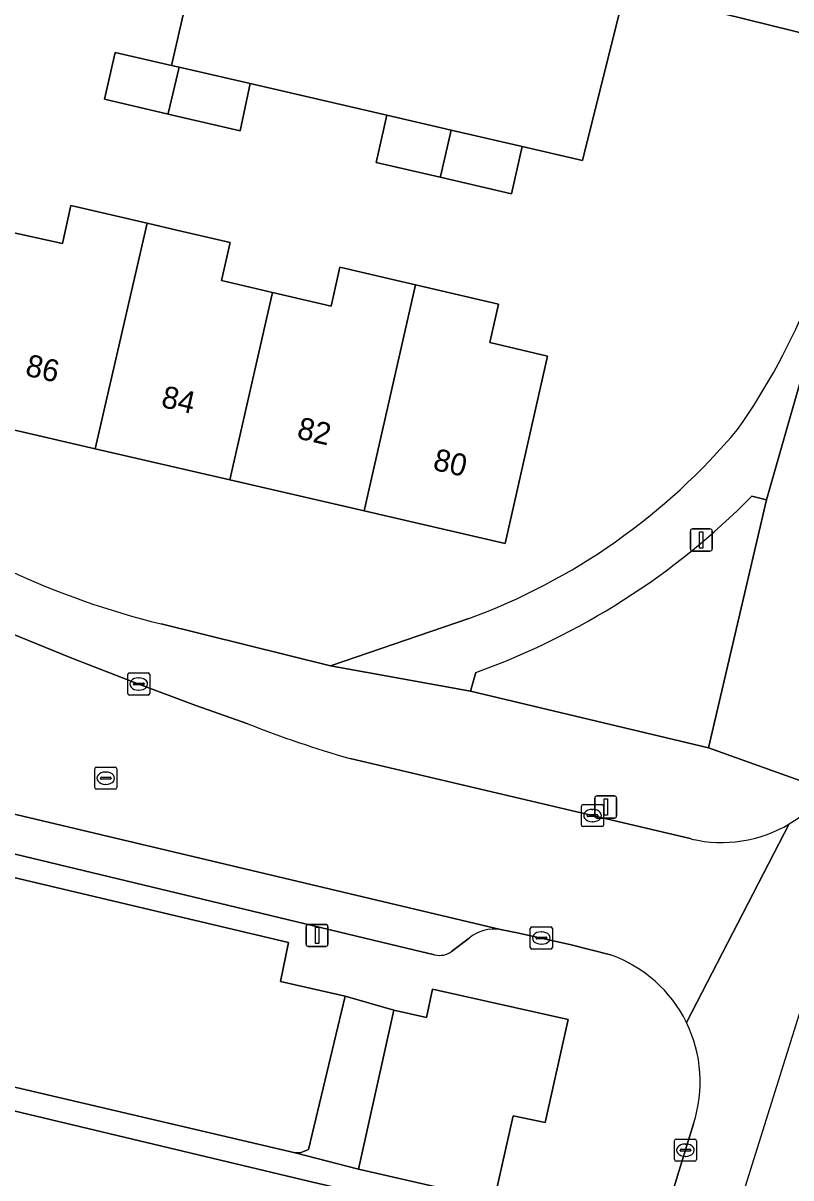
# Model space of a CAD drawing. Extents: x 163008 to 163854, y 382777 to 383982.
# Drawn here: x 163763.6 to 163798.5, y 383354.9 to 383407.3 of the extents above; entities that cross this region are included whole.
import ezdxf

# ---------------------------------------------------------------- set-up
doc = ezdxf.new("R2010")
doc.units = 0
for name, color, linetype in [('IMGEO_Erf', 7, 'Continuous'), ('IMGEO_Groenvoorziening', 7, 'Continuous'), ('IMGEO_Kolk', 7, 'Continuous'), ('IMGEO_Lichtmast', 7, 'Continuous'), ('IMGEO_Pand', 7, 'Continuous'), ('IMGEO_Pand_nummerreeks', 7, 'Continuous'), ('IMGEO_Parkeervlak_open', 7, 'Continuous'), ('IMGEO_Rijbaan_lokaal_open', 7, 'Continuous'), ('IMGEO_Rioolput', 7, 'Continuous'), ('IMGEO_Voetpad_open', 7, 'Continuous')]:
    doc.layers.add(name, color=color, linetype=linetype)

msp = doc.modelspace()

# ---------------------------------------------------------------- linework, layer by layer
at = {"layer": 'IMGEO_Erf'}
for points in [[(163799.368, 383395.016), (163801.187, 383399.458), (163801.918, 383401.615), (163802.959, 383405.824), (163790.935, 383408.798), (163789.014, 383401.029), (163786.266, 383401.666), (163785.784, 383399.527), (163782.556, 383400.276), (163779.658, 383400.949), (163780.144, 383403.084), (163773.939, 383404.523), (163773.49, 383402.383), (163770.226, 383403.141), (163767.333, 383403.812), (163767.819, 383405.932), (163770.382, 383405.342), (163773.071, 383417.032)], [(163769.902, 383380.045), (163777.588, 383378.149), (163783.852, 383380.28)]]:
    msp.add_lwpolyline(points, dxfattribs=at)
msp.add_lwpolyline([(163785.2, 383394.532), (163784.808, 383392.787), (163787.427, 383392.166), (163785.498, 383383.681), (163779.107, 383385.158), (163773.021, 383386.564), (163766.916, 383387.975), (163760.863, 383389.374), (163762.82, 383397.842), (163765.432, 383397.271), (163765.812, 383398.998), (163769.272, 383398.198), (163770.684, 383397.871), (163773.034, 383397.327), (163772.646, 383395.595), (163774.953, 383395.054), (163777.615, 383394.429), (163778, 383396.199), (163780.329, 383395.66), (163781.443, 383395.402)], close=True, dxfattribs=at)
for centre, radius, start, end in [((163772.159, 383405.74), 29.246, 324.7245, 338.4891), ((163773.895, 383407.38), 28.871, 290.1749, 320.0732), ((163778.941, 383416.87), 37.918, 234.0301, 256.2094)]:
    msp.add_arc(centre, radius, start, end, dxfattribs=at)
at = {"layer": 'IMGEO_Groenvoorziening'}
for points in [[(163784.165, 383377.842), (163783.938, 383376.989), (163794.715, 383374.433), (163797.353, 383385.666), (163796.685, 383385.825)], [(163747.804, 383373.109), (163755.296, 383361.078), (163755.433, 383360.934), (163755.642, 383360.831), (163775.986, 383356.078), (163776.249, 383356.094), (163776.592, 383356.226), (163778.246, 383363.18), (163775.319, 383363.846), (163775.685, 383365.603), (163755.491, 383370.375), (163748.307, 383374.117)]]:
    msp.add_lwpolyline(points, dxfattribs=at)
msp.add_lwpolyline([(163785.862, 383357.756), (163787.31, 383357.457), (163788.359, 383362.117), (163782.206, 383363.494), (163781.932, 383362.217), (163780.455, 383362.549), (163778.857, 383355.345), (163784.998, 383353.934)], close=True, dxfattribs=at)
msp.add_arc((163772.866, 383409.372), 33.494, 289.7159, 315.3289, dxfattribs=at)
at = {"layer": 'IMGEO_Kolk'}
for p, q in [((163768.392, 383376.892), (163768.392, 383377.744)), ((163768.467, 383377.818), (163769.319, 383377.818)), ((163768.88, 383377.598), (163768.905, 383377.598)), ((163769.393, 383377.744), (163769.393, 383376.892)), ((163768.651, 383377.312), (163768.651, 383377.324)), ((163769.089, 383377.275), (163768.691, 383377.275)), ((163768.694, 383377.361), (163769.092, 383377.361)), ((163768.903, 383377.038), (163768.878, 383377.038)), ((163769.135, 383377.324), (163769.135, 383377.312)), ((163769.319, 383376.818), (163768.467, 383376.818)), ((163788.962, 383370.931), (163788.962, 383371.783)), ((163789.037, 383371.857), (163789.889, 383371.857)), ((163789.963, 383371.783), (163789.963, 383370.931)), ((163789.221, 383371.351), (163789.221, 383371.363)), ((163789.659, 383371.314), (163789.261, 383371.314)), ((163789.264, 383371.4), (163789.662, 383371.4)), ((163789.45, 383371.637), (163789.475, 383371.637)), ((163789.705, 383371.363), (163789.705, 383371.351)), ((163789.889, 383370.857), (163789.037, 383370.857)), ((163789.473, 383371.077), (163789.448, 383371.077)), ((163786.642, 383365.386), (163786.642, 383366.238)), ((163786.717, 383366.312), (163787.569, 383366.312)), ((163787.13, 383366.092), (163787.155, 383366.092)), ((163787.643, 383366.238), (163787.643, 383365.386)), ((163786.901, 383365.806), (163786.901, 383365.818)), ((163787.339, 383365.769), (163786.941, 383365.769)), ((163786.944, 383365.855), (163787.342, 383365.855)), ((163787.153, 383365.532), (163787.128, 383365.532)), ((163787.385, 383365.818), (163787.385, 383365.806)), ((163787.569, 383365.312), (163786.717, 383365.312)), ((163793.173, 383355.772), (163793.173, 383356.624)), ((163793.248, 383356.698), (163794.1, 383356.698)), ((163794.174, 383356.624), (163794.174, 383355.772)), ((163793.432, 383356.192), (163793.432, 383356.204)), ((163793.87, 383356.155), (163793.472, 383356.155)), ((163793.475, 383356.241), (163793.873, 383356.241)), ((163793.661, 383356.478), (163793.686, 383356.478)), ((163793.916, 383356.204), (163793.916, 383356.192)), ((163794.1, 383355.698), (163793.248, 383355.698)), ((163793.684, 383355.918), (163793.659, 383355.918))]:
    msp.add_line(p, q, dxfattribs=at)
for points in [[(163768.392, 383376.892), (163768.392, 383377.744)], [(163768.467, 383377.818), (163769.319, 383377.818)], [(163769.393, 383377.744), (163769.393, 383376.892)], [(163769.319, 383376.818), (163768.467, 383376.818)], [(163788.962, 383370.931), (163788.962, 383371.783)], [(163789.037, 383371.857), (163789.889, 383371.857)], [(163789.963, 383371.783), (163789.963, 383370.931)], [(163789.889, 383370.857), (163789.037, 383370.857)], [(163786.642, 383365.386), (163786.642, 383366.238)], [(163786.717, 383366.312), (163787.569, 383366.312)], [(163787.643, 383366.238), (163787.643, 383365.386)], [(163787.569, 383365.312), (163786.717, 383365.312)], [(163793.173, 383355.772), (163793.173, 383356.624)], [(163793.248, 383356.698), (163794.1, 383356.698)], [(163794.174, 383356.624), (163794.174, 383355.772)], [(163794.1, 383355.698), (163793.248, 383355.698)]]:
    msp.add_lwpolyline(points, dxfattribs=at)
for centre, radius, start, end in [((163768.469, 383377.742), 0.0765, 91.552, 178.448), ((163768.469, 383377.742), 0.0765, 91.552, 178.448), ((163769.317, 383377.742), 0.0765, 1.552, 88.448), ((163769.317, 383377.742), 0.0765, 1.552, 88.448), ((163768.469, 383376.894), 0.0765, 181.552, 268.448), ((163768.469, 383376.894), 0.0765, 181.552, 268.448), ((163768.691, 383377.321), 0.0403, 85.8775, 175.7526), ((163768.688, 383377.311), 0.0366, 178.938, 274.7102), ((163769.092, 383377.318), 0.043, 264.8664, 352.4533), ((163769.096, 383377.323), 0.0386, 1.7309, 96.639), ((163769.317, 383376.894), 0.0765, 271.552, 358.448), ((163769.317, 383376.894), 0.0765, 271.552, 358.448), ((163789.039, 383371.781), 0.0765, 91.552, 178.448), ((163789.039, 383371.781), 0.0765, 91.552, 178.448), ((163789.887, 383371.781), 0.0765, 1.552, 88.448), ((163789.887, 383371.781), 0.0765, 1.552, 88.448), ((163789.261, 383371.36), 0.0403, 85.8775, 175.7526), ((163789.258, 383371.35), 0.0366, 178.938, 274.7102), ((163789.662, 383371.357), 0.043, 264.8664, 352.4533), ((163789.666, 383371.362), 0.0386, 1.7309, 96.639), ((163789.039, 383370.933), 0.0765, 181.552, 268.448), ((163789.039, 383370.933), 0.0765, 181.552, 268.448), ((163789.887, 383370.933), 0.0765, 271.552, 358.448), ((163789.887, 383370.933), 0.0765, 271.552, 358.448), ((163786.719, 383366.236), 0.0765, 91.552, 178.448), ((163786.719, 383366.236), 0.0765, 91.552, 178.448), ((163787.567, 383366.236), 0.0765, 1.552, 88.448), ((163787.567, 383366.236), 0.0765, 1.552, 88.448), ((163786.719, 383365.388), 0.0765, 181.552, 268.448), ((163786.719, 383365.388), 0.0765, 181.552, 268.448), ((163786.941, 383365.815), 0.0403, 85.8775, 175.7526), ((163786.938, 383365.805), 0.0366, 178.938, 274.7102), ((163787.342, 383365.812), 0.043, 264.8664, 352.4533), ((163787.346, 383365.817), 0.0386, 1.7309, 96.639), ((163787.567, 383365.388), 0.0765, 271.552, 358.448), ((163787.567, 383365.388), 0.0765, 271.552, 358.448), ((163793.25, 383356.622), 0.0765, 91.552, 178.448), ((163793.25, 383356.622), 0.0765, 91.552, 178.448), ((163794.098, 383356.622), 0.0765, 1.552, 88.448), ((163794.098, 383356.622), 0.0765, 1.552, 88.448), ((163793.472, 383356.201), 0.0403, 85.8775, 175.7526), ((163793.469, 383356.191), 0.0366, 178.938, 274.7102), ((163793.873, 383356.198), 0.043, 264.8664, 352.4533), ((163793.877, 383356.203), 0.0386, 1.7309, 96.639), ((163793.25, 383355.774), 0.0765, 181.552, 268.448), ((163793.25, 383355.774), 0.0765, 181.552, 268.448), ((163794.098, 383355.774), 0.0765, 271.552, 358.448), ((163794.098, 383355.774), 0.0765, 271.552, 358.448)]:
    msp.add_arc(centre, radius, start, end, dxfattribs=at)
for centre, major_axis, ratio, start_param, end_param in [((163768.879, 383377.318), (-0.387, 0.002), 0.722429, 4.712389, 7.853982), ((163768.904, 383377.318), (-0.39, 0.002), 0.717154, 1.570796, 4.712389), ((163789.449, 383371.357), (-0.387, 0.002), 0.722429, 4.712389, 7.853982), ((163789.474, 383371.357), (-0.39, 0.002), 0.717154, 1.570796, 4.712389), ((163787.129, 383365.812), (-0.387, 0.002), 0.722429, 4.712389, 7.853982), ((163787.154, 383365.812), (-0.39, 0.002), 0.717154, 1.570796, 4.712389), ((163793.66, 383356.198), (-0.387, 0.002), 0.722429, 4.712389, 7.853982), ((163793.685, 383356.198), (-0.39, 0.002), 0.717154, 1.570796, 4.712389)]:
    msp.add_ellipse(centre, major_axis=major_axis, ratio=ratio, start_param=start_param, end_param=end_param, dxfattribs=at)
at = {"layer": 'IMGEO_Lichtmast'}
for p, q in [((163793.897, 383383.443), (163793.897, 383384.243)), ((163793.897, 383384.243), (163793.897, 383383.443)), ((163793.997, 383384.343), (163794.787, 383384.343)), ((163794.787, 383384.343), (163793.997, 383384.343)), ((163794.887, 383384.243), (163794.887, 383383.443)), ((163794.887, 383383.443), (163794.887, 383384.243)), ((163794.787, 383383.343), (163793.997, 383383.343)), ((163793.997, 383383.343), (163794.787, 383383.343)), ((163789.664, 383372.247), (163790.454, 383372.247)), ((163790.454, 383372.247), (163789.664, 383372.247)), ((163789.564, 383371.347), (163789.564, 383372.147)), ((163789.564, 383372.147), (163789.564, 383371.347)), ((163790.554, 383372.147), (163790.554, 383371.347)), ((163790.554, 383371.347), (163790.554, 383372.147)), ((163790.454, 383371.247), (163789.664, 383371.247)), ((163789.664, 383371.247), (163790.454, 383371.247)), ((163776.578, 383366.431), (163777.368, 383366.431)), ((163777.368, 383366.431), (163776.578, 383366.431)), ((163776.478, 383365.531), (163776.478, 383366.331)), ((163776.478, 383366.331), (163776.478, 383365.531)), ((163777.468, 383366.331), (163777.468, 383365.531)), ((163777.468, 383365.531), (163777.468, 383366.331)), ((163777.368, 383365.431), (163776.578, 383365.431)), ((163776.578, 383365.431), (163777.368, 383365.431))]:
    msp.add_line(p, q, dxfattribs=at)
for points in [[(163794.317, 383384.218), (163794.467, 383384.218), (163794.467, 383383.468), (163794.317, 383383.468), (163794.317, 383384.218)], [(163789.984, 383372.122), (163790.134, 383372.122), (163790.134, 383371.372), (163789.984, 383371.372), (163789.984, 383372.122)], [(163776.898, 383366.306), (163777.048, 383366.306), (163777.048, 383365.556), (163776.898, 383365.556), (163776.898, 383366.306)]]:
    msp.add_lwpolyline(points, dxfattribs=at)
for centre, start, end in [((163793.997, 383384.243), 90, 180), ((163793.997, 383384.243), 90, 180), ((163794.787, 383384.243), 0, 90), ((163794.787, 383384.243), 360, 90), ((163793.997, 383383.443), 180, 270), ((163793.997, 383383.443), 180, 270), ((163794.787, 383383.443), 270, 0), ((163794.787, 383383.443), 270, 0), ((163789.664, 383372.147), 90, 180), ((163789.664, 383372.147), 90, 180), ((163790.454, 383372.147), 0, 90), ((163790.454, 383372.147), 360, 90), ((163789.664, 383371.347), 180, 270), ((163789.664, 383371.347), 180, 270), ((163790.454, 383371.347), 270, 0), ((163790.454, 383371.347), 270, 0), ((163776.578, 383366.331), 90, 180), ((163776.578, 383366.331), 90, 180), ((163777.368, 383366.331), 0, 90), ((163777.368, 383366.331), 360, 90), ((163776.578, 383365.531), 180, 270), ((163776.578, 383365.531), 180, 270), ((163777.368, 383365.531), 270, 0), ((163777.368, 383365.531), 270, 0)]:
    msp.add_arc(centre, 0.1, start, end, dxfattribs=at)
at = {"layer": 'IMGEO_Pand'}
for points in [[(163770.718, 383405.265), (163770.382, 383405.342), (163767.819, 383405.932), (163767.333, 383403.812), (163770.226, 383403.141), (163770.232, 383403.171)], [(163770.226, 383403.141), (163773.49, 383402.383), (163773.939, 383404.523), (163770.718, 383405.265), (163770.232, 383403.171)], [(163782.556, 383400.276), (163782.564, 383400.31), (163783.051, 383402.411), (163780.144, 383403.084), (163779.658, 383400.949)], [(163782.556, 383400.276), (163785.784, 383399.527), (163786.266, 383401.666), (163783.051, 383402.411), (163782.564, 383400.31)], [(163769.272, 383398.198), (163765.812, 383398.998), (163765.432, 383397.271), (163762.82, 383397.842), (163760.863, 383389.374), (163766.916, 383387.975)], [(163769.272, 383398.198), (163766.916, 383387.975), (163773.021, 383386.564), (163774.953, 383395.054), (163772.646, 383395.595), (163773.034, 383397.327), (163770.684, 383397.871)], [(163781.443, 383395.402), (163780.329, 383395.66), (163778, 383396.199), (163777.615, 383394.429), (163774.953, 383395.054), (163773.021, 383386.564), (163779.107, 383385.158)], [(163781.443, 383395.402), (163779.107, 383385.158), (163785.498, 383383.681), (163787.427, 383392.166), (163784.808, 383392.787), (163785.2, 383394.532)]]:
    msp.add_lwpolyline(points, close=True, dxfattribs=at)
at = {"layer": 'IMGEO_Parkeervlak_open'}
for points in [[(163785.291, 383366.2), (163753.811, 383373.652)], [(163755.98, 383371.367), (163781.025, 383365.351), (163782.304, 383365.05)], [(163783.069, 383365.194), (163783.868, 383365.808)]]:
    msp.add_lwpolyline(points, dxfattribs=at)
for centre, radius, start, end in [((163785.03, 383364.367), 1.851, 81.911, 128.892), ((163782.524, 383365.984), 0.96, 256.734, 304.5867)]:
    msp.add_arc(centre, radius, start, end, dxfattribs=at)
at = {"layer": 'IMGEO_Rijbaan_lokaal_open'}
for points in [[(163803.888, 383409.582), (163776.948, 383416.246), (163773.071, 383417.032), (163770.382, 383405.342), (163770.718, 383405.265), (163773.939, 383404.523), (163780.144, 383403.084), (163783.051, 383402.411), (163786.266, 383401.666), (163789.014, 383401.029), (163790.935, 383408.798), (163802.959, 383405.824)], [(163776.589, 383354.796), (163754.535, 383360.053), (163753.411, 383355.265), (163775.252, 383350.11), (163787.56, 383347.183), (163789.027, 383351.896), (163784.762, 383352.89)]]:
    msp.add_lwpolyline(points, close=True, dxfattribs=at)
for points in [[(163773.838, 383375.516), (163771.472, 383376.352), (163768.889, 383377.317), (163765.862, 383378.489), (163763.076, 383379.628)], [(163750.958, 383374.454), (163752.575, 383373.983), (163753.811, 383373.652), (163785.291, 383366.2), (163786.119, 383366.034), (163788.492, 383365.5), (163790.279, 383365.043)], [(163793.952, 383370.297), (163789.776, 383371.28), (163778.48, 383373.938)], [(163794.04, 383357.394), (163792.602, 383352.734), (163794.08, 383352.273), (163792.677, 383347.837), (163794.181, 383347.493), (163800.501, 383367.676), (163801.841, 383371.957)], [(163793.719, 383361.985), (163798.38, 383370.98)], [(163798.38, 383370.98), (163793.719, 383361.985)]]:
    msp.add_lwpolyline(points, dxfattribs=at)
for centre, radius, start, end in [((163791.912, 383421.069), 49.008, 248.3578, 254.0923), ((163795.318, 383376.103), 5.968, 300.8686, 322.9155), ((163795.323, 383376.102), 5.965, 256.7082, 300.8288), ((163788.249, 383359.296), 6.095, 26.1798, 70.549), ((163788.243, 383359.295), 6.101, 341.8406, 26.1585)]:
    msp.add_arc(centre, radius, start, end, dxfattribs=at)
at = {"layer": 'IMGEO_Rioolput'}
for p, q in [((163766.894, 383372.625), (163766.894, 383373.477)), ((163766.969, 383373.551), (163767.821, 383373.551)), ((163767.382, 383373.331), (163767.407, 383373.331)), ((163767.895, 383373.477), (163767.895, 383372.625)), ((163767.153, 383373.045), (163767.153, 383373.057)), ((163767.591, 383373.008), (163767.193, 383373.008)), ((163767.196, 383373.094), (163767.594, 383373.094)), ((163767.405, 383372.771), (163767.38, 383372.771)), ((163767.637, 383373.057), (163767.637, 383373.045)), ((163767.821, 383372.551), (163766.969, 383372.551))]:
    msp.add_line(p, q, dxfattribs=at)
for points in [[(163766.894, 383372.625), (163766.894, 383373.477)], [(163766.969, 383373.551), (163767.821, 383373.551)], [(163767.895, 383373.477), (163767.895, 383372.625)], [(163767.821, 383372.551), (163766.969, 383372.551)]]:
    msp.add_lwpolyline(points, dxfattribs=at)
for centre, radius, start, end in [((163766.971, 383373.475), 0.0765, 91.552, 178.448), ((163766.971, 383373.475), 0.0765, 91.552, 178.448), ((163767.819, 383373.475), 0.0765, 1.552, 88.448), ((163767.819, 383373.475), 0.0765, 1.552, 88.448), ((163767.193, 383373.054), 0.0403, 85.8775, 175.7526), ((163767.19, 383373.044), 0.0366, 178.938, 274.7102), ((163767.594, 383373.051), 0.043, 264.8664, 352.4533), ((163767.598, 383373.056), 0.0386, 1.7309, 96.639), ((163766.971, 383372.627), 0.0765, 181.552, 268.448), ((163766.971, 383372.627), 0.0765, 181.552, 268.448), ((163767.819, 383372.627), 0.0765, 271.552, 358.448), ((163767.819, 383372.627), 0.0765, 271.552, 358.448)]:
    msp.add_arc(centre, radius, start, end, dxfattribs=at)
for centre, major_axis, ratio, start_param, end_param in [((163767.381, 383373.051), (-0.387, 0.002), 0.722429, 4.712389, 7.853982), ((163767.406, 383373.051), (-0.39, 0.002), 0.717154, 1.570796, 4.712389)]:
    msp.add_ellipse(centre, major_axis=major_axis, ratio=ratio, start_param=start_param, end_param=end_param, dxfattribs=at)
at = {"layer": 'IMGEO_Voetpad_open'}
for points in [[(163803.888, 383409.582), (163802.959, 383405.824), (163801.918, 383401.615), (163797.353, 383385.666), (163794.715, 383374.433), (163800.079, 383372.504)], [(163796.685, 383385.825), (163797.353, 383385.666), (163801.918, 383401.615), (163801.187, 383399.458), (163799.368, 383395.016)], [(163726.156, 383384.266), (163743.748, 383374.739), (163748.307, 383374.117), (163755.491, 383370.375), (163775.685, 383365.603), (163775.319, 383363.846), (163778.246, 383363.18), (163780.455, 383362.549), (163781.932, 383362.217), (163782.206, 383363.494), (163788.359, 383362.117), (163787.31, 383357.457), (163785.862, 383357.756), (163784.998, 383353.934), (163784.762, 383352.89), (163789.027, 383351.896), (163791.701, 383351.323), (163792.125, 383351.191), (163792.602, 383352.734), (163794.04, 383357.394)], [(163783.938, 383376.989), (163777.588, 383378.149), (163769.902, 383380.045)], [(163783.852, 383380.28), (163777.588, 383378.149), (163783.938, 383376.989), (163784.165, 383377.842)], [(163763.076, 383379.628), (163765.862, 383378.489), (163768.889, 383377.317), (163771.472, 383376.352), (163773.838, 383375.516)], [(163800.079, 383372.504), (163794.715, 383374.433), (163783.938, 383376.989)], [(163778.48, 383373.938), (163789.776, 383371.28), (163793.952, 383370.297)], [(163706.496, 383371.33), (163751.936, 383360.663), (163754.535, 383360.053), (163776.589, 383354.796), (163784.762, 383352.89), (163784.998, 383353.934), (163778.857, 383355.345), (163775.986, 383356.078), (163755.642, 383360.831), (163755.433, 383360.934), (163755.296, 383361.078), (163751.725, 383362.155)], [(163782.304, 383365.05), (163781.025, 383365.351), (163755.98, 383371.367)], [(163790.279, 383365.043), (163788.492, 383365.5), (163786.119, 383366.034), (163785.291, 383366.2)], [(163783.868, 383365.808), (163783.069, 383365.194)]]:
    msp.add_lwpolyline(points, dxfattribs=at)
msp.add_lwpolyline([(163780.455, 383362.549), (163778.246, 383363.18), (163776.592, 383356.226), (163776.249, 383356.094), (163775.986, 383356.078), (163778.857, 383355.345)], close=True, dxfattribs=at)
for centre, radius, start, end in [((163772.159, 383405.74), 29.246, 324.7245, 338.4891), ((163773.895, 383407.38), 28.871, 290.1749, 320.0732), ((163778.941, 383416.87), 37.918, 234.0301, 256.2094), ((163772.866, 383409.372), 33.494, 289.7159, 315.3289), ((163791.912, 383421.069), 49.008, 248.3578, 254.0923), ((163795.318, 383376.103), 5.968, 300.8686, 322.9155), ((163795.323, 383376.102), 5.965, 256.7082, 300.8288), ((163785.03, 383364.367), 1.851, 81.911, 128.892), ((163782.524, 383365.984), 0.96, 256.734, 304.5867), ((163788.249, 383359.296), 6.095, 26.1798, 70.549), ((163788.243, 383359.295), 6.101, 341.8406, 26.1585)]:
    msp.add_arc(centre, radius, start, end, dxfattribs=at)

# ---------------------------------------------------------------- texts
at = {"layer": 'IMGEO_Pand_nummerreeks'}
for s, p in [('86', (163763.704, 383391.304)), ('84', (163769.863, 383389.881)), ('82', (163776.019, 383388.457)), ('80', (163782.184, 383387.033))]:
    msp.add_text(s, height=1, rotation=346.9877, dxfattribs=at).set_placement(p)

doc.saveas('drawing.dxf')
